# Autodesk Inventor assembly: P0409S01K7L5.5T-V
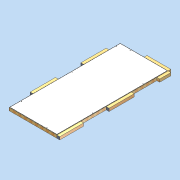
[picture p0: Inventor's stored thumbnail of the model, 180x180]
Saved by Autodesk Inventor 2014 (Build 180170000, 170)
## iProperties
Created: 2011-04
Part Number: P0409S01K7L5.5T-V
Document SubType Name: Assembly
Designer: david.appleford
Description: 1w x 2.25w  01 Panel - 7 Locks 5.5 Lugs
Mass: 52000 g
Surface Area: 77195.9 cm^2
Volume: 260791 cm^3
Density: 0.199393 g/cm^3
Cost Center: £178.00
Justset: False
Title: 1w x 2.25w  01 Panel - 7 Locks 5.5 Lugs
Author: david.appleford
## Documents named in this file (5)
- C:\Documents and Settings\john.everitt\Local Settings\My Documents\Vault\Production MkII\VIRTUAL ELEMENTS\Virtual Walls\Virtual Timber + MgO\P0409S01K7L5.5T-V.iam
- C:\Documents and Settings\john.everitt\Local Settings\My Documents\Vault\Production MkII\VIRTUAL ELEMENTS\Virtual Lugs\Superceded Lugs\LA02C3V.ipt
- C:\Documents and Settings\john.everitt\Local Settings\My Documents\Vault\Production MkII\VIRTUAL ELEMENTS\Virtual Lugs\Superceded Lugs\LA02M3V.ipt
- C:\Documents and Settings\john.everitt\Local Settings\My Documents\Vault\Production MkII\Virtual Elements\Virtual Walls\Virtual Timber + MgO\P0409S01K7-V.ipt
- C:\Documents and Settings\john.everitt\Local Settings\My Documents\Vault\Production MkII\VIRTUAL ELEMENTS\Virtual Lugs\Superceded Lugs\LA01C3V.ipt
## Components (7 placed, 4 different names)
1. P0409S01K7-V:1 — Mate:1, Flush:1, Flush:2, Mate:4, Flush:7, Flush:8, Mate:5, Mate:6, Flush:9, Flush:10, Mate:7, Flush:11, Mate:14, Flush:12, Flush:13
2. LA02C3V:1 — Mate:1, Flush:1, Flush:2, Mate:9, Mate:13
3. LA02C3V:3 — Mate:4, Flush:7, Flush:8
4. LA02M3V:5 — Mate:6, Flush:9, Mate:12
5. LA02M3V:2 — Mate:5, Flush:10, Mate:12, Mate:13
6. LA02M3V:4 — Mate:7, Flush:11, Mate:9
7. LA01C3V:1 — Mate:14, Flush:12, Flush:13
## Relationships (18: Mate 9, Flush 9)
- Mate:1: P0409S01K7-V:1 ↔ LA02C3V:1
- Flush:1: P0409S01K7-V:1 ↔ LA02C3V:1
- Flush:2: P0409S01K7-V:1 ↔ LA02C3V:1
- Mate:4: P0409S01K7-V:1 ↔ LA02C3V:3
- Flush:7: P0409S01K7-V:1 ↔ LA02C3V:3
- Flush:8: P0409S01K7-V:1 ↔ LA02C3V:3
- Mate:5: P0409S01K7-V:1 ↔ LA02M3V:2
- Mate:6: P0409S01K7-V:1 ↔ LA02M3V:5
- Flush:9: P0409S01K7-V:1 ↔ LA02M3V:5
- Flush:10: P0409S01K7-V:1 ↔ LA02M3V:2
- Mate:7: P0409S01K7-V:1 ↔ LA02M3V:4
- Flush:11: P0409S01K7-V:1 ↔ LA02M3V:4
- Mate:9: LA02C3V:1 ↔ LA02M3V:4
- Mate:12: LA02M3V:5 ↔ LA02M3V:2
- Mate:13: LA02C3V:1 ↔ LA02M3V:2
- Mate:14: P0409S01K7-V:1 ↔ LA01C3V:1
- Flush:12: P0409S01K7-V:1 ↔ LA01C3V:1
- Flush:13: P0409S01K7-V:1 ↔ LA01C3V:1
## Named parameters: t = 1 mm, Cl = 2 mm
